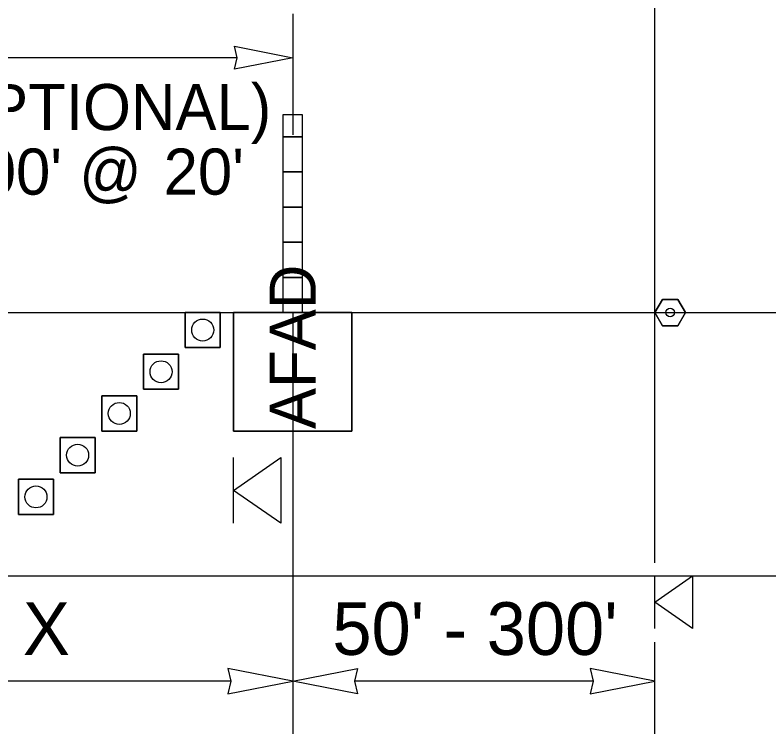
# Model space of a CAD drawing. Extents: x 99999.1 to 100095.7, y 99995 to 100010.7.
# Drawn here: x 100043.855 to 100045, y 100005.492 to 100006.584 of the extents above; entities that cross this region are included whole.
import ezdxf

# ---------------------------------------------------------------- set-up
doc = ezdxf.new("R2010")
doc.units = 0
for name, color, linetype in [('RD_ED_ShoulderPavedEdge', 7, 'Continuous'), ('RD_MK_LineEdgeWhite', 7, 'Continuous'), ('TR_WZ_AFAD', 7, 'Continuous'), ('TR_WZ_PortableSignMountBlk-Wht', 7, 'Continuous'), ('TR_WZ_TrafficCone', 7, 'Continuous'), ('TR_WZ_TubularMarker', 7, 'Continuous'), ('TR_WZ_WorkZoneDetails', 7, 'Continuous'), ('TR_WZ_WorkZoneTextCurrent', 7, 'Continuous')]:
    doc.layers.add(name, color=color, linetype=linetype)

msp = doc.modelspace()

# ---------------------------------------------------------------- linework, layer by layer
at = {"layer": 'RD_ED_ShoulderPavedEdge'}
msp.add_line((100040.1076, 100005.7323), (100055.6424, 100005.7323), dxfattribs=at)
at = {"layer": 'RD_MK_LineEdgeWhite'}
msp.add_line((100040.1076, 100006.1323), (100055.6424, 100006.1323), dxfattribs=at)
at = {"layer": 'TR_WZ_AFAD'}
for p, q in [((100044.2916, 100006.399), (100044.2916, 100006.4323)), ((100044.2616, 100006.399), (100044.2616, 100006.3457)), ((100044.2616, 100006.399), (100044.2766, 100006.399)), ((100044.2766, 100006.399), (100044.2916, 100006.399)), ((100044.2916, 100006.3457), (100044.2916, 100006.399)), ((100044.2616, 100006.3457), (100044.2616, 100006.2923)), ((100044.2766, 100006.3457), (100044.2616, 100006.3457)), ((100044.2916, 100006.3457), (100044.2766, 100006.3457)), ((100044.2916, 100006.2923), (100044.2916, 100006.3457)), ((100044.2616, 100006.2923), (100044.2616, 100006.239)), ((100044.2616, 100006.2923), (100044.2766, 100006.2923)), ((100044.2766, 100006.2923), (100044.2916, 100006.2923)), ((100044.2916, 100006.239), (100044.2916, 100006.2923)), ((100044.2766, 100006.239), (100044.2616, 100006.239)), ((100044.2616, 100006.239), (100044.2616, 100006.1857)), ((100044.2916, 100006.239), (100044.2766, 100006.239)), ((100044.2916, 100006.1857), (100044.2916, 100006.239)), ((100044.2616, 100006.1857), (100044.2616, 100006.1323)), ((100044.1866, 100005.9523), (100044.1866, 100006.1323)), ((100044.1866, 100006.1323), (100044.3666, 100006.1323)), ((100044.27, 100006.1323), (100044.1866, 100006.1323)), ((100044.1866, 100006.1323), (100044.1866, 100005.9523)), ((100044.2616, 100006.1323), (100044.27, 100006.1323)), ((100044.27, 100006.1323), (100044.2766, 100006.1323)), ((100044.3666, 100006.1323), (100044.3666, 100005.9523)), ((100044.3666, 100005.9523), (100044.3666, 100006.1323)), ((100044.3666, 100005.9523), (100044.1866, 100005.9523)), ((100044.1866, 100005.9523), (100044.3666, 100005.9523))]:
    msp.add_line(p, q, dxfattribs=at)
for points in [[(100044.2916, 100006.4323), (100044.2616, 100006.4323), (100044.2616, 100006.399)], [(100044.2916, 100006.1323), (100044.2916, 100006.4323), (100044.2616, 100006.4323), (100044.2616, 100006.1323)], [(100044.2916, 100006.399), (100044.2766, 100006.399), (100044.2616, 100006.399)], [(100044.2616, 100006.3457), (100044.2766, 100006.3457), (100044.2916, 100006.3457)], [(100044.2916, 100006.2923), (100044.2766, 100006.2923), (100044.2616, 100006.2923)], [(100044.2616, 100006.239), (100044.2766, 100006.239), (100044.2916, 100006.239)], [(100044.2916, 100006.1857), (100044.2766, 100006.1857), (100044.2616, 100006.1857)], [(100044.2616, 100006.1857), (100044.2766, 100006.1857), (100044.2916, 100006.1857)], [(100044.2766, 100006.1323), (100044.2833, 100006.1323), (100044.2916, 100006.1323), (100044.2916, 100006.1857)], [(100044.3666, 100006.1323), (100044.2833, 100006.1323), (100044.27, 100006.1323)]]:
    msp.add_lwpolyline(points, dxfattribs=at)
at = {"layer": 'TR_WZ_PortableSignMountBlk-Wht'}
for p, q in [((100044.1867, 100005.8123), (100044.1867, 100005.9123)), ((100044.8267, 100005.6523), (100044.8267, 100005.7323))]:
    msp.add_line(p, q, dxfattribs=at)
for points in [[(100044.1867, 100005.8622), (100044.2585, 100005.9123), (100044.2585, 100005.8123)], [(100044.8267, 100005.6923), (100044.8841, 100005.7323), (100044.8841, 100005.6523)]]:
    msp.add_lwpolyline(points, close=True, dxfattribs=at)
at = {"layer": 'TR_WZ_TrafficCone'}
for points in [[(100044.1133, 100006.1323), (100044.1667, 100006.1323), (100044.1667, 100006.079), (100044.1133, 100006.079), (100044.1133, 100006.1323)], [(100044.1133, 100006.079), (100044.1667, 100006.079), (100044.1667, 100006.1323), (100044.1133, 100006.1323), (100044.1133, 100006.079)], [(100044.05, 100006.069), (100044.1033, 100006.069), (100044.1033, 100006.0157), (100044.05, 100006.0157), (100044.05, 100006.069)], [(100044.05, 100006.0157), (100044.1033, 100006.0157), (100044.1033, 100006.069), (100044.05, 100006.069), (100044.05, 100006.0157)], [(100043.9867, 100006.0057), (100044.04, 100006.0057), (100044.04, 100005.9523), (100043.9867, 100005.9523), (100043.9867, 100006.0057)], [(100043.9867, 100005.9523), (100044.04, 100005.9523), (100044.04, 100006.0057), (100043.9867, 100006.0057), (100043.9867, 100005.9523)], [(100043.9767, 100005.9423), (100043.9233, 100005.9423), (100043.9233, 100005.889), (100043.9767, 100005.889), (100043.9767, 100005.9423)], [(100043.9767, 100005.889), (100043.9233, 100005.889), (100043.9233, 100005.9423), (100043.9767, 100005.9423), (100043.9767, 100005.889)], [(100043.9133, 100005.879), (100043.86, 100005.879), (100043.86, 100005.8257), (100043.9133, 100005.8257), (100043.9133, 100005.879)], [(100043.9133, 100005.8257), (100043.86, 100005.8257), (100043.86, 100005.879), (100043.9133, 100005.879), (100043.9133, 100005.8257)]]:
    msp.add_lwpolyline(points, dxfattribs=at)
for centre in [(100044.14, 100006.1057), (100044.0767, 100006.0423), (100044.0133, 100005.979), (100043.95, 100005.9157), (100043.8867, 100005.8523)]:
    msp.add_circle(centre, 0.0167, dxfattribs=at)
at = {"layer": 'TR_WZ_TubularMarker'}
msp.add_lwpolyline([(100044.8269, 100006.1323), (100044.8385, 100006.1523), (100044.8616, 100006.1523), (100044.8731, 100006.1323), (100044.8616, 100006.1123), (100044.8385, 100006.1123)], close=True, dxfattribs=at)
msp.add_lwpolyline([(100044.8385, 100006.1123), (100044.8616, 100006.1123), (100044.8731, 100006.1323), (100044.8616, 100006.1523), (100044.8385, 100006.1523), (100044.8269, 100006.1323), (100044.8385, 100006.1123)], dxfattribs=at)
msp.add_circle((100044.85, 100006.1323), 0.00667, dxfattribs=at)
at = {"layer": 'TR_WZ_WorkZoneDetails'}
for p, q in [((100044.8267, 100005.7523), (100044.8267, 100007.7323)), ((100044.2767, 100006.5857), (100044.2767, 100006.4023)), ((100044.1923, 100006.5193), (100043.761, 100006.5193)), ((100044.2767, 100006.1323), (100044.2767, 100005.4923)), ((100044.8267, 100005.4923), (100044.8267, 100005.6319)), ((100044.1829, 100005.5723), (100043.6204, 100005.5723)), ((100044.7329, 100005.5723), (100044.3704, 100005.5723))]:
    msp.add_line(p, q, dxfattribs=at)
for points in [[(100044.2767, 100006.5193), (100044.1882, 100006.502), (100044.1923, 100006.5193), (100044.1882, 100006.5367)], [(100044.2767, 100005.5723), (100044.1784, 100005.5916), (100044.1829, 100005.5723), (100044.1784, 100005.5531)], [(100044.2767, 100005.5723), (100044.3749, 100005.5916), (100044.3704, 100005.5723), (100044.3749, 100005.5531)], [(100044.8267, 100005.5723), (100044.7284, 100005.5916), (100044.7329, 100005.5723), (100044.7284, 100005.5531)]]:
    msp.add_lwpolyline(points, close=True, dxfattribs=at)

# ---------------------------------------------------------------- texts
at = {"layer": 'TR_WZ_AFAD'}
msp.add_text('AFAD', height=0.07, rotation=90, dxfattribs=at).set_placement((100044.3116, 100005.9553))
at = {"layer": 'TR_WZ_WorkZoneTextCurrent'}
for s, p in [('(OPTIONAL)', (100043.7085, 100006.4093)), ("300' @", (100043.7523, 100006.3113)), ("20'", (100044.0807, 100006.3113))]:
    msp.add_text(s, height=0.07, dxfattribs=at).set_placement(p)
for s, p in [('X', (100043.8669, 100005.6123)), ("50' - 300'", (100044.3369, 100005.6123))]:
    msp.add_text(s, height=0.08, rotation=360, dxfattribs=at).set_placement(p)

doc.saveas('drawing.dxf')
